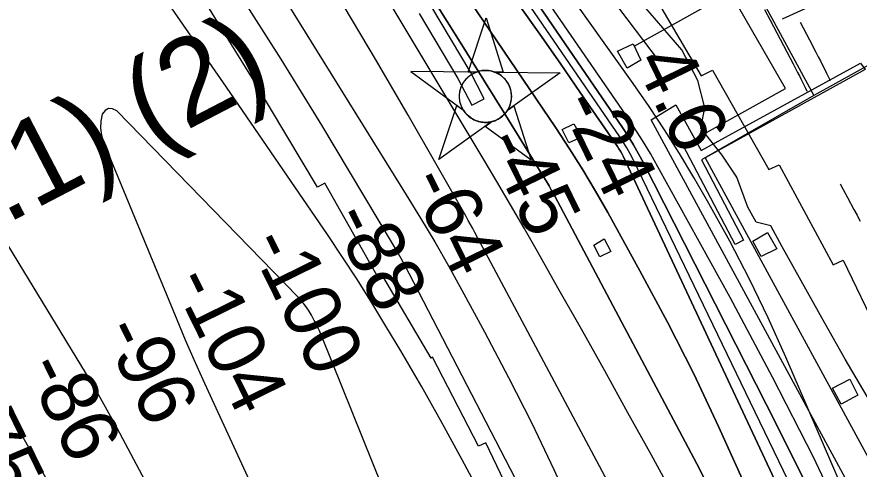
# Model space of a CAD drawing. Extents: x 3568792 to 3606828, y 529143 to 554785.
# Drawn here: x 3576994 to 3577982, y 540044 to 540574 of the extents above; entities that cross this region are included whole.
import ezdxf

# ---------------------------------------------------------------- set-up
doc = ezdxf.new("R2010")
doc.units = 0
for name, color, linetype in [('V-CHAN-DOCK', 7, 'Continuous'), ('V-CHAN-NAID', 7, 'Continuous'), ('V-RIVR-EDGE', 7, 'Continuous'), ('V-RIVR-RANG', 7, 'Continuous'), ('V-ROAD-CNTR', 7, 'Continuous'), ('V-RRAP-RVMT', 7, 'Continuous'), ('V-TOPO-DPTH', 7, 'Continuous'), ('V-TOPO-MAJR', 7, 'Continuous'), ('V-TOPO-MINR', 7, 'Continuous'), ('V-TOPO-WATR', 7, 'Continuous'), ('V-UTIL-LINE', 7, 'Continuous')]:
    doc.layers.add(name, color=color, linetype=linetype)

msp = doc.modelspace()

# ---------------------------------------------------------------- linework, layer by layer
at = {"layer": 'V-CHAN-DOCK'}
for points in [[(3577465.48, 540578.37), (3577511.02, 540502.28), (3577527.41, 540470.85), (3577541.99, 540478.13), (3577525.6, 540510.48), (3577480.51, 540585.65)], [(3577709.64, 540514.09), (3577698.25, 540534.14), (3577716.48, 540542.79), (3577725.59, 540523.66), (3577709.64, 540514.09)], [(3577801.14, 540409.04), (3578047.9, 539955.18), (3578018.42, 539935.37), (3577737.67, 540453.46), (3577766.52, 540471.36), (3577796.31, 540417.75), (3577983.19, 540520.02), (3577988.83, 540512.84), (3577801.14, 540409.04)], [(3577647.22, 540448.96), (3577655.87, 540433.47), (3577641.29, 540426.64), (3577633.55, 540442.13), (3577647.22, 540448.96)], [(3577874.06, 540321.36), (3577884.99, 540302.23), (3577866.77, 540293.12), (3577857.2, 540311.35), (3577874.06, 540321.36)], [(3577682.73, 540314.11), (3577690.47, 540299.08), (3577677.71, 540292.7), (3577670.43, 540306.37), (3577682.73, 540314.11)], [(3577970.61, 540149.15), (3577980.17, 540130.47), (3577960.58, 540120), (3577950.56, 540138.68), (3577970.61, 540149.15)]]:
    msp.add_lwpolyline(points, dxfattribs=at)
at = {"layer": 'V-CHAN-NAID'}
for points in [[(3577532.54, 540509.65), (3577522.96, 540509.72), (3577544.08, 540573.2), (3577564.31, 540509.42), (3577554.72, 540509.49), (3577553.14, 540510.07), (3577551.05, 540510.69), (3577549.01, 540511.14), (3577546.97, 540511.45), (3577545.81, 540511.56), (3577544.27, 540511.64), (3577542.55, 540511.64), (3577541.18, 540511.57), (3577539.27, 540511.37), (3577537.91, 540511.15), (3577536.12, 540510.77), (3577534.59, 540510.35), (3577533.56, 540510.02)], [(3577532.54, 540509.65), (3577456.05, 540510.19), (3577517.62, 540464.79), (3577516.51, 540466.7), (3577515.7, 540468.33), (3577514.87, 540470.3), (3577514.18, 540472.35), (3577513.81, 540473.67), (3577513.45, 540475.3), (3577513.21, 540476.74), (3577513.02, 540478.34), (3577512.91, 540480.08), (3577512.9, 540481.66), (3577513, 540483.73), (3577513.19, 540485.35), (3577513.58, 540487.55), (3577514.06, 540489.48), (3577514.66, 540491.36), (3577515.32, 540493.04), (3577516.04, 540494.63), (3577516.86, 540496.17), (3577517.92, 540497.9), (3577518.95, 540499.37), (3577519.95, 540500.64), (3577520.95, 540501.79), (3577522.26, 540503.13), (3577523.31, 540504.09), (3577525.03, 540505.49), (3577526.24, 540506.36), (3577527.93, 540507.43), (3577529.66, 540508.37), (3577531.1, 540509.06)], [(3577554.72, 540509.49), (3577631.21, 540508.95), (3577569.01, 540464.43), (3577569.92, 540465.92), (3577570.9, 540467.76), (3577571.61, 540469.35), (3577572.35, 540471.3), (3577572.9, 540473.09), (3577573.3, 540474.73), (3577573.66, 540476.74), (3577573.84, 540478.31), (3577573.97, 540480.52), (3577573.94, 540482.58), (3577573.75, 540484.8), (3577573.48, 540486.56), (3577572.99, 540488.79), (3577572.35, 540490.93), (3577571.6, 540492.91), (3577570.95, 540494.35), (3577569.95, 540496.27), (3577568.89, 540497.99), (3577567.67, 540499.69), (3577566.41, 540501.23), (3577565.14, 540502.6), (3577563.51, 540504.13), (3577561.76, 540505.54), (3577560.08, 540506.72), (3577558.19, 540507.85), (3577556.72, 540508.61)], [(3577550.98, 540451.52), (3577488.78, 540407), (3577509.9, 540470.48), (3577517.62, 540464.79), (3577518.25, 540463.83), (3577519.64, 540461.97), (3577520.85, 540460.55), (3577522.32, 540459.05), (3577523.71, 540457.8), (3577525.16, 540456.64), (3577526.56, 540455.66), (3577528.24, 540454.62), (3577529.95, 540453.71), (3577531.75, 540452.9), (3577533.19, 540452.34), (3577534.82, 540451.81), (3577537.04, 540451.25), (3577538.58, 540450.96), (3577540.6, 540450.7), (3577542.14, 540450.6), (3577544, 540450.58), (3577545.69, 540450.66), (3577547.4, 540450.83), (3577549.3, 540451.14)], [(3577569.01, 540464.43), (3577576.81, 540470.01), (3577597.03, 540406.23), (3577543.18, 540445.94), (3577550.98, 540451.52), (3577552.65, 540452), (3577554.26, 540452.56), (3577556.42, 540453.47), (3577558.15, 540454.35), (3577560.02, 540455.47), (3577561.75, 540456.68), (3577563.31, 540457.93), (3577564.59, 540459.09), (3577565.98, 540460.51), (3577567.18, 540461.92), (3577568.3, 540463.39)]]:
    msp.add_lwpolyline(points, close=True, dxfattribs=at)
msp.add_circle((3577543.43, 540481.11), 30.54, dxfattribs=at)
at = {"layer": 'V-RIVR-EDGE'}
msp.add_lwpolyline([(3578007.96, 540100.28), (3577965.24, 540172.69), (3577941.45, 540215.03), (3577891.43, 540304.61), (3577878.01, 540329.15), (3577860.86, 540333.48), (3577851.11, 540351.27), (3577838.32, 540386.23), (3577821.23, 540412.01), (3577796.19, 540443.93), (3577800.54, 540467.82), (3577792.65, 540499.7), (3577773.75, 540535.9), (3577729.14, 540587.48)], dxfattribs=at)
at = {"layer": 'V-ROAD-CNTR'}
for points in [[(3577900.86, 541302.2), (3577967.15, 541113.95), (3577995.94, 541020.97), (3578038.75, 540895.55), (3578048.72, 540856.91), (3578059.45, 540824.39), (3578074.67, 540747.91), (3578077.4, 540716.58), (3578078.74, 540684.73), (3578078.75, 540667.39), (3578072.44, 540657.84), (3578054.01, 540646.08), (3577891.34, 540571.71)], [(3577870.57, 540583.17), (3577877.16, 540570.76), (3577896.89, 540533.41), (3577904.42, 540519.15), (3577907.19, 540513.84), (3577909.6, 540509.2), (3577911.67, 540505.14), (3577913.45, 540501.61), (3577916.54, 540495.38), (3577918.78, 540490.71), (3577920.45, 540487.16)], [(3577912.52, 540568.05), (3577923.42, 540547.42), (3577930.97, 540533.11), (3577933.81, 540527.69), (3577936.27, 540522.93), (3577938.42, 540518.73), (3577940.29, 540515.02), (3577943.5, 540508.53), (3577945.87, 540503.6), (3577947.6, 540499.93)], [(3577959.43, 540378.3), (3577960.04, 540377.14), (3577962.94, 540371.72), (3577968.02, 540362.38), (3577975.59, 540348.49), (3577979.3, 540341.59), (3577981.12, 540338.16), (3577982.92, 540334.71)]]:
    msp.add_lwpolyline(points, dxfattribs=at)
at = {"layer": 'V-RRAP-RVMT'}
for p, q in [((3577729.73, 540619.05), (3577796.25, 540505.06)), ((3577273.43, 540496.86), (3577206.36, 540605.47)), ((3577796.25, 540505.06), (3577809.65, 540511.8)), ((3577809.65, 540511.8), (3577875.73, 540395.47)), ((3577346.28, 540374.75), (3577273.43, 540496.86)), ((3577875.73, 540395.47), (3577887.96, 540400.99)), ((3577887.96, 540400.99), (3577951.09, 540283.68)), ((3577355.04, 540379.21), (3577346.28, 540374.75)), ((3577418.02, 540267.96), (3577355.04, 540379.21)), ((3577951.09, 540283.68), (3577963.02, 540289.05)), ((3577963.02, 540289.05), (3578021.44, 540167.12)), ((3577423.22, 540270.22), (3577418.02, 540267.96)), ((3577479.84, 540174.04), (3577423.22, 540270.22)), ((3577481.45, 540175.11), (3577479.84, 540174.04)), ((3577535.26, 540070.59), (3577481.45, 540175.11)), ((3577543.86, 540074.61), (3577535.26, 540070.59)), ((3577594.97, 539968.59), (3577543.86, 540074.61))]:
    msp.add_line(p, q, dxfattribs=at)
at = {"layer": 'V-TOPO-DPTH'}
for points in [[(3577946.83, 539971.36), (3577885.36, 540095.19), (3577728.74, 540403.14), (3577723.04, 540413.83), (3577717.07, 540424.35), (3577710.69, 540434.64), (3577704.05, 540444.77), (3577453.97, 540810.15), (3577403.34, 540883.64), (3577352.41, 540956.92), (3577301.04, 541029.89), (3577249.37, 541102.64), (3577221.17, 541142.09), (3577183.11, 541194.77), (3577144.7, 541247.2), (3577105.76, 541299.23), (3577066.47, 541351.01), (3577021.24, 541409.99), (3577004.13, 541431.94), (3576986.79, 541453.71)], [(3576986.79, 541453.71), (3577004.13, 541431.94), (3577021.24, 541409.99), (3577066.47, 541351.01), (3577105.76, 541299.23), (3577144.7, 541247.2), (3577183.11, 541194.77), (3577221.17, 541142.09), (3577249.37, 541102.64), (3577301.04, 541029.89), (3577352.41, 540956.92), (3577403.34, 540883.64), (3577453.97, 540810.15), (3577704.05, 540444.77), (3577710.69, 540434.64), (3577717.07, 540424.35), (3577723.04, 540413.83), (3577728.74, 540403.14), (3577885.36, 540095.19), (3577946.83, 539971.36)], [(3576951.48, 541422.46), (3577463.62, 540623.57), (3577489.77, 540582.56), (3577515.77, 540541.46), (3577541.56, 540500.22), (3577567.22, 540458.9), (3577611.18, 540387.68), (3577614.69, 540381.87), (3577618.12, 540376.01), (3577621.44, 540370.09), (3577624.67, 540364.13), (3577791.24, 540049.8), (3577853.97, 539928.06)], [(3576951.48, 541422.46), (3577463.62, 540623.57), (3577489.77, 540582.56), (3577515.77, 540541.46), (3577541.56, 540500.22), (3577567.22, 540458.9), (3577611.18, 540387.68), (3577614.69, 540381.87), (3577618.12, 540376.01), (3577621.44, 540370.09), (3577624.67, 540364.13), (3577791.24, 540049.8), (3577853.97, 539928.06)], [(3576965.7, 541419.54), (3577214.5, 541052.59), (3577288.62, 540943.2), (3577362.7, 540833.78), (3577436.71, 540724.32), (3577510.68, 540614.83), (3577625.89, 540444.17), (3577641.89, 540419.78), (3577657.45, 540395.13), (3577672.35, 540370.07), (3577686.81, 540344.74), (3577724.64, 540276.41), (3577756.78, 540216.27), (3577787.71, 540155.54), (3577816.83, 540093.91), (3577844.73, 540031.69)], [(3577844.73, 540031.69), (3577816.83, 540093.91), (3577787.71, 540155.54), (3577756.78, 540216.27), (3577724.64, 540276.41), (3577686.81, 540344.74), (3577672.35, 540370.07), (3577657.45, 540395.13), (3577641.89, 540419.78), (3577625.89, 540444.17), (3577510.68, 540614.83), (3577436.71, 540724.32), (3577362.7, 540833.78), (3577288.62, 540943.2), (3577214.5, 541052.59), (3576965.7, 541419.54)], [(3576980.63, 541417.12), (3577105.12, 541247.84), (3577175.58, 541151.73), (3577245.85, 541055.49), (3577315.82, 540959.03), (3577385.61, 540862.44), (3577558.7, 540622.08), (3577582.96, 540588.17), (3577607.06, 540554.16), (3577630.95, 540519.99), (3577654.69, 540485.72), (3577698.17, 540422.52), (3577699.99, 540419.73), (3577701.71, 540416.89), (3577703.29, 540413.97), (3577704.77, 540410.99), (3578151.77, 539455.67)], [(3578151.77, 539455.67), (3577704.77, 540410.99), (3577703.29, 540413.97), (3577701.71, 540416.89), (3577699.99, 540419.73), (3577698.17, 540422.52), (3577654.69, 540485.72), (3577630.95, 540519.99), (3577607.06, 540554.16), (3577582.96, 540588.17), (3577558.7, 540622.08), (3577385.61, 540862.44), (3577315.82, 540959.03), (3577245.85, 541055.49), (3577175.58, 541151.73), (3577105.12, 541247.84), (3576980.63, 541417.12)], [(3578230.73, 539398.14), (3577895.91, 540175.25), (3577875.13, 540221.23), (3577853.3, 540266.68), (3577829.88, 540311.33), (3577805.41, 540355.46), (3577787.69, 540386.12), (3577770.89, 540414.27), (3577753.57, 540442.07), (3577735.46, 540469.37), (3577716.83, 540496.34), (3577097.5, 541365.84)]]:
    msp.add_lwpolyline(points, dxfattribs=at)
at = {"layer": 'V-TOPO-MAJR'}
for points in [[(3577754.93, 540029.29), (3577737.6, 540060.94), (3577710.58, 540110.01), (3577683.42, 540158.99), (3577656.03, 540207.85), (3577628.49, 540256.63), (3577604.45, 540298.97), (3577588.72, 540326.46), (3577572.86, 540353.86), (3577556.8, 540381.15), (3577540.61, 540408.37), (3577038.24, 541245.98), (3577020.19, 541274.94), (3577001.49, 541303.46), (3576981.82, 541331.33)], [(3577101.21, 540467.09), (3577097.29, 540464.59), (3577093.84, 540460.13), (3577092.25, 540451.89), (3577091.79, 540443.71), (3577093.03, 540435.6), (3577095.4, 540427.55), (3577181.46, 540219.18), (3577191.34, 540195.66), (3577201.42, 540172.22), (3577211.79, 540148.91), (3577222.35, 540125.68), (3577350.8, 539847.66)], [(3577755.89, 539194.93), (3577351.35, 540199.49), (3577348.64, 540205.85), (3577345.76, 540212.12), (3577342.64, 540218.27), (3577339.34, 540224.34), (3577335.71, 540230.19), (3577331.8, 540235.83), (3577327.48, 540241.15), (3577322.87, 540246.27), (3577110.96, 540464.28), (3577105.85, 540466.66), (3577101.21, 540467.09)]]:
    msp.add_lwpolyline(points, dxfattribs=at)
at = {"layer": 'V-TOPO-MINR'}
for points in [[(3577746.18, 540523.76), (3576758.02, 541827.6)], [(3577973.07, 539962.31), (3577928.04, 540057.76), (3577880.21, 540151.83), (3577830.51, 540244.99), (3577745.75, 540398.4), (3577736.81, 540414.02), (3577727.57, 540429.46), (3577717.89, 540444.63), (3577707.9, 540459.6), (3577278.42, 541083.82), (3577248.26, 541127.42), (3577217.95, 541170.92), (3577187.43, 541214.27), (3577156.76, 541257.51), (3577139.14, 541282.22), (3577116.97, 541312.88), (3577094.53, 541343.35), (3577071.68, 541373.51), (3577048.57, 541403.46), (3577046.76, 541405.77), (3577024.14, 541434.25), (3577001.24, 541462.51), (3576977.93, 541490.42)], [(3577946.83, 539971.36), (3577885.36, 540095.19), (3577728.74, 540403.14), (3577723.04, 540413.83), (3577717.07, 540424.35), (3577710.69, 540434.64), (3577704.05, 540444.77), (3577453.97, 540810.15), (3577403.34, 540883.64), (3577352.41, 540956.92), (3577301.04, 541029.89), (3577249.37, 541102.64), (3577221.17, 541142.09), (3577183.11, 541194.77), (3577144.7, 541247.2), (3577105.76, 541299.23), (3577066.47, 541351.01), (3577021.24, 541409.99), (3577004.13, 541431.94), (3576986.79, 541453.71)], [(3578019.72, 539779.37), (3577716.57, 540406.97), (3577713.06, 540413.84), (3577709.34, 540420.6), (3577705.32, 540427.18), (3577701.1, 540433.64), (3577596.62, 540585.96), (3577539.75, 540668.31), (3577482.53, 540750.42), (3577424.81, 540832.18), (3577366.74, 540913.69), (3577303.3, 541002.15), (3577249.37, 541076.82), (3577195.12, 541151.24), (3577140.37, 541225.3), (3577085.28, 541299.12), (3576999.1, 541413.81), (3576986.73, 541429.99)], [(3577853.97, 539928.06), (3577791.24, 540049.8), (3577624.67, 540364.13), (3577621.44, 540370.09), (3577618.12, 540376.01), (3577614.69, 540381.87), (3577611.18, 540387.68), (3577567.22, 540458.9), (3577541.56, 540500.22), (3577515.77, 540541.46), (3577489.77, 540582.56), (3577463.62, 540623.57), (3576951.48, 541422.46)], [(3577844.73, 540031.69), (3577816.83, 540093.91), (3577787.71, 540155.54), (3577756.78, 540216.27), (3577724.64, 540276.41), (3577686.81, 540344.74), (3577672.35, 540370.07), (3577657.45, 540395.13), (3577641.89, 540419.78), (3577625.89, 540444.17), (3577510.68, 540614.83), (3577436.71, 540724.32), (3577362.7, 540833.78), (3577288.62, 540943.2), (3577214.5, 541052.59), (3576965.7, 541419.54)], [(3578151.77, 539455.67), (3577704.77, 540410.99), (3577703.29, 540413.97), (3577701.71, 540416.89), (3577699.99, 540419.73), (3577698.17, 540422.52), (3577654.69, 540485.72), (3577630.95, 540519.99), (3577607.06, 540554.16), (3577582.96, 540588.17), (3577558.7, 540622.08), (3577385.61, 540862.44), (3577315.82, 540959.03), (3577245.85, 541055.49), (3577175.58, 541151.73), (3577105.12, 541247.84), (3576980.63, 541417.12)], [(3577708.29, 539988.4), (3577531.06, 540321.44), (3577528.5, 540326.2), (3577525.92, 540330.93), (3577523.29, 540335.65), (3577520.63, 540340.34), (3577452.62, 540459.22), (3577415.45, 540523.04), (3577377.61, 540586.46), (3577338.79, 540649.28), (3577299.3, 540711.71), (3576877.04, 541367.82)], [(3576961.11, 541140.75), (3577009.51, 541070.61), (3577056.32, 540999.39), (3577102.07, 540927.46), (3577450.5, 540365.79), (3577467.33, 540338.13), (3577483.84, 540310.29), (3577499.87, 540282.16), (3577515.58, 540253.86), (3577542.29, 540204.74), (3577570.46, 540151.41), (3577597.74, 540097.65), (3577623.71, 540043.24), (3577648.79, 539988.39), (3577954.28, 539298.38), (3577966.1, 539270.69), (3577977.41, 539242.81), (3577987.97, 539214.63), (3577998.03, 539186.26), (3578182.76, 538642.19), (3578203.09, 538579.61), (3578222.3, 538516.72), (3578239.83, 538453.33)], [(3577612.36, 539967.27), (3577454.01, 540273.2), (3577449.27, 540282.16), (3577444.41, 540291.06), (3577439.4, 540299.87), (3577434.28, 540308.63), (3577351.3, 540447.46), (3577303.69, 540524.98), (3577254.86, 540601.71), (3577204.19, 540677.23), (3577152.29, 540751.95), (3576997.15, 540969.68), (3576971.71, 541005.16)], [(3577539.21, 540011.73), (3577516.24, 540054.87), (3577492.8, 540097.74), (3577468.64, 540140.21), (3577444, 540182.42), (3577426.69, 540211.53), (3577410.1, 540238.82), (3577393.17, 540265.89), (3577375.73, 540292.64), (3577357.95, 540319.16), (3577239.65, 540492.08), (3577161.93, 540604.53), (3577083.5, 540716.47), (3577004.01, 540827.67), (3576923.81, 540938.36)], [(3576967.3, 540331.82), (3577079.26, 540148.09), (3577087.49, 540134.31), (3577095.56, 540120.44), (3577103.37, 540106.42), (3577111.01, 540092.31), (3577211.75, 539902.37), (3577268.76, 539792.79), (3577324.61, 539682.63), (3577378.72, 539571.6), (3577431.66, 539459.99), (3577577.52, 539146.12), (3577588.97, 539121.31), (3577600.34, 539096.47), (3577611.6, 539071.57), (3577622.77, 539046.64), (3577683.94, 538909.23), (3577724.96, 538815.28), (3577765.05, 538720.95), (3577803.78, 538626.05), (3577841.59, 538530.76), (3577968.87, 538203.09)], [(3576988.71, 540101.6), (3576996.43, 540088.68), (3577004.03, 540075.69), (3577011.44, 540062.59), (3577018.73, 540049.42), (3577116.8, 539869.22)]]:
    msp.add_lwpolyline(points, dxfattribs=at)
at = {"layer": 'V-TOPO-WATR'}
msp.add_lwpolyline([(3578230.73, 539398.14), (3577895.91, 540175.25), (3577875.13, 540221.23), (3577853.3, 540266.68), (3577829.88, 540311.33), (3577805.41, 540355.46), (3577787.69, 540386.12), (3577770.89, 540414.27), (3577753.57, 540442.07), (3577735.46, 540469.37), (3577716.83, 540496.34), (3577097.5, 541365.84)], dxfattribs=at)
at = {"layer": 'V-UTIL-LINE'}
for p, q in [((3578184.19, 540623.7), (3577928.66, 540482.35)), ((3577717.86, 540539.89), (3577830.54, 540603.11))]:
    msp.add_line(p, q, dxfattribs=at)
msp.add_lwpolyline([(3576899.06, 542734.31), (3576676.72, 542553.04), (3576687.19, 542529.81), (3576714.01, 542192.24), (3576712.64, 542152.61), (3576814.67, 542062.84), (3576853.83, 541990.41), (3576995.46, 541712.95), (3577068.77, 541567.62), (3577195.85, 541433.66), (3577417.66, 541206.31), (3577668.62, 540944.32), (3577682.75, 540937.03), (3577793.41, 540731.56), (3577928.66, 540482.35), (3577796.99, 540406.75), (3577846.18, 540312.44), (3577836.15, 540307.43), (3577775.13, 540423.61), (3577895.41, 540490.55), (3577807.97, 540642.27), (3577659.05, 540916.08), (3577640.38, 540921.09)], dxfattribs=at)

# ---------------------------------------------------------------- texts
at = {"layer": 'V-CHAN-NAID'}
for s, p in [('VALERO NO. 4 ', (3576355.38, 540284)), (' (125.1) (2)', (3576710.62, 540190.17))]:
    msp.add_text(s, height=100, rotation=27.49284, dxfattribs=at).set_placement(p)
at = {"layer": 'V-RIVR-RANG'}
for s, rotation, p in [('4.6', 295.91833, (3577717.5, 540521.92)), ('-24', 296.20261, (3577630.03, 540472.2)), ('-45', 296.20261, (3577540.78, 540427.08)), ('-64', 296.20261, (3577451.76, 540381.49)), ('-88', 296.20261, (3577361.11, 540339.22)), ('-100', 296.20261, (3577264.41, 540309.25)), ('-104', 296.20261, (3577175.04, 540264.37)), ('-96', 296.20261, (3577092.31, 540206)), ('-86', 296.20261, (3577002.01, 540163.01)), ('-75', 296.20261, (3576911.71, 540120.03))]:
    msp.add_text(s, height=67, rotation=rotation, dxfattribs=at).set_placement(p)

doc.saveas('drawing.dxf')
